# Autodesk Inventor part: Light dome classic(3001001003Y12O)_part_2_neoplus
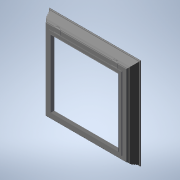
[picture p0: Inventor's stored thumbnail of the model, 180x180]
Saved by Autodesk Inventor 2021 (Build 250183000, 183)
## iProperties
Created: 2026-04
Part Number: Light dome classic(3001001003Y12O)_part_2_neoplus
Material: Generic
Catalog Web Link: www.3dfindit.com
Description: Light dome classic_part_2_neoplus-
Vendor: KINGSPAN
Document SubType Name: Modeling
Designer: psAdmin
Manufacturer: KINGSPAN
Mass: 9326.02 g
Surface Area: 18698.6 cm^2
Volume: 9326.02 cm^3
Density: 1 g/cm^3
Appearance: PSOLRGB-255-255-255
Category: PARTsolutions
Company: KINGSPAN
Title: Light dome classic(3001001003Y12O)_part_2_neoplus
Author: Cadenas PARTsolutions
PSOL_IDENT_0: {$CADENAS_DATA/23d-libs/kingspan_kla/light_dome_classic_neoplus/parts/part_2.prj},293 {VTYP=3D},{NB=
PSOL_IDENT_1: Light dome classic(3001001003Y12O)_part_2_neoplus},{LINA=Light dome classic(3001001003Y12O)_part_2_n
PSOL_IDENT_2: eoplus},{NN=Light dome classic_part_2_neoplus},{DATE=20.03.2025 09:30:52},{GEOMDATE=01.07.2024 06:23
PSOL_IDENT_3: :48},{VERSION=},{LINEID=10},{WBVAR=LODLEVEL,L,W,BA,SF,DP,OP,OC},{WBNUMERIC=W}  {NB=Light dome classi
PSOL_IDENT_4: c(3001001003Y12O)_part_2_neoplus},{LINA=Light dome classic(3001001003Y12O)_part_2_neoplus},{KT=DUMMY
PSOL_IDENT_5: },{IDNR=},{PN=Light dome classic},{LODLEVEL=300},{L=100},{W=100},{WX=100,150,200,250,300},{LX=1000},
PSOL_IDENT_6: {XWX=1000},{BA=3},{SF=Y},{SFX='Y','Yes','N','No'},{DRIVE=1},{DPX='1', 'Natural ventilation', '2' , '
PSOL_IDENT_7: NSHEV (natural smoke, heat exhaust ventilation)', '3', 'Fixed','4','NSHE'},{DP=1},{OPX='1','manualy'
PSOL_IDENT_8: ,'2','Linear drive 300 mm stroke 24 V and 230 V','3','Linear drive 500 mm stroke 24 V and 230 V'},{O
PSOL_IDENT_9: P=2},{OCX='O', 'Open', 'C', 'Closed'},{OC=O}
NB: Light dome classic(3001001003Y12O)_part_2_neoplus
NN: Light dome classic_part_2_neoplus
NBSYN: $PN.($LODLEVEL.$L.$W.$BA.$SF.$DP.$OP.$OC.)_part_2_neoplus
LINA: Light dome classic(3001001003Y12O)_part_2_neoplus
CATALOG: Light + Air
PN: Light dome classic
LODLEVEL: 300
L: 100
W: 100
BA: PVC base 50 cm
SF: Yes
DP: Natural ventilation
OP: Linear drive 300 mm stroke 24 V and 230 V
OC: Open
SUPPLIER: KINGSPAN
ARTICLENO: Light dome classic(3001001003Y12O)_part_2_neoplus
BOMINFO: Light dome classic(3001001003Y12O)_part_2_neoplus
CREATOR: CADENAS GmbH
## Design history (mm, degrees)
sketch "Sketch_1"
  geometry: L1 (-393, 334)-(-395.2, 334); L2 (-395.2, 334)-(-395.2, 327); L3 (-395.2, 327)-(-424, 327); L4 (-424, 327)-(-424, 316); L5 (-424, 316)-(-467.8, 316); L6 (-472, 311.8)-(-472, 306.773); L7 (-477, 298.113)-(-489.32, 291); L8 (-489.32, 291)-(-500.849, 274.535); L9 (-500.849, 274.535)-(-496.754, 271.668); L10 (-496.754, 271.668)-(-508.226, 255.284); L11 (-508.226, 255.284)-(-504.129, 252.415); L12 (-504.129, 252.415)-(-515.6, 236.032); L13 (-515.6, 236.032)-(-511.507, 233.166); L14 (-511.507, 233.166)-(-521.208, 219.311); L15 (-521.208, 219.311)-(-532.773, 219.311); L16 (-532.773, 219.311)-(-532.773, 204.131); L17 (-532.773, 204.131)-(-525.173, 204.131); L18 (-519.959, 217.26)-(-508.443, 233.706); L19 (-508.443, 233.706)-(-512.536, 236.572); L20 (-512.536, 236.572)-(-501.065, 252.955); L21 (-501.065, 252.955)-(-505.162, 255.824); L22 (-505.162, 255.824)-(-493.69, 272.208); L23 (-493.69, 272.208)-(-497.785, 275.075); L24 (-497.785, 275.075)-(-487.798, 289.339); L25 (-487.798, 289.339)-(-481.456, 293); L26 (-481.456, 293)-(-393, 293); L27 (-393, 293)-(-393, 334); A1 r 4.2 centre (-467.8, 311.8) between (-467.8, 316) and (-472, 311.8); A2 r 10 centre (-482, 306.773) between (-477, 298.113) and (-472, 306.773); A3 r 7.6 centre (-525.173, 211.731) between (-525.173, 204.131) and (-519.959, 217.26)
  constraints: 54 end point, 6 point on circle, 3 centre point
extrude "Extrusion1" join sketch "Sketch_1" stored distance "d0" = 2000; taper "d1" = 0 deg
sketch "Sketch_2"
  geometry: L1 (395.2, 334)-(393, 334); L2 (393, 334)-(393, 293); L3 (393, 293)-(481.456, 293); L4 (481.456, 293)-(487.798, 289.339); L5 (487.798, 289.339)-(497.785, 275.075); L6 (497.785, 275.075)-(493.69, 272.208); L7 (493.69, 272.208)-(505.162, 255.824); L8 (505.162, 255.824)-(501.065, 252.955); L9 (501.065, 252.955)-(512.536, 236.572); L10 (512.536, 236.572)-(508.443, 233.706); L11 (508.443, 233.706)-(519.959, 217.26); L12 (525.173, 204.131)-(532.77, 204.131); L13 (532.77, 204.131)-(532.77, 219.311); L14 (532.77, 219.311)-(521.208, 219.311); L15 (521.208, 219.311)-(511.507, 233.166); L16 (511.507, 233.166)-(515.6, 236.032); L17 (515.6, 236.032)-(504.129, 252.415); L18 (504.129, 252.415)-(508.226, 255.284); L19 (508.226, 255.284)-(496.754, 271.668); L20 (496.754, 271.668)-(500.849, 274.535); L21 (500.849, 274.535)-(489.32, 291); L22 (489.32, 291)-(477, 298.113); L23 (472, 306.773)-(472, 311.8); L24 (467.8, 316)-(424, 316); L25 (424, 316)-(424, 327); L26 (424, 327)-(395.2, 327); L27 (395.2, 327)-(395.2, 334); A1 r 7.6 centre (525.173, 211.731) between (519.959, 217.26) and (525.173, 204.131); A2 r 10 centre (482, 306.773) between (472, 306.773) and (477, 298.113); A3 r 4.2 centre (467.8, 311.8) between (472, 311.8) and (467.8, 316)
  constraints: 54 end point, 6 point on circle, 3 centre point
extrude "Extrusion2" join sketch "Sketch_2" stored distance "d2" = 2000; taper "d3" = 0 deg
sketch "Sketch_3"
  geometry: L1 (534.773, 204.131)-(534.773, 219.311); L2 (534.773, 219.311)-(521.208, 219.311); L3 (521.208, 219.311)-(511.507, 233.166); L4 (511.507, 233.166)-(515.6, 236.032); L5 (515.6, 236.032)-(504.129, 252.415); L6 (504.129, 252.415)-(508.226, 255.284); L7 (508.226, 255.284)-(496.754, 271.668); L8 (496.754, 271.668)-(500.849, 274.535); L9 (500.849, 274.535)-(489.32, 291); L10 (489.32, 291)-(477, 298.113); L11 (472, 306.773)-(472, 311.8); L12 (467.8, 316)-(424, 316); L13 (424, 316)-(424, 327); L14 (424, 327)-(395.2, 327); L15 (395.2, 327)-(395.2, 334); L16 (395.2, 334)-(393, 334); L17 (393, 334)-(393, 293); L18 (393, 293)-(481.456, 293); L19 (481.456, 293)-(487.798, 289.339); L20 (487.798, 289.339)-(497.785, 275.075); L21 (497.785, 275.075)-(493.69, 272.208); L22 (493.69, 272.208)-(505.162, 255.824); L23 (505.162, 255.824)-(501.065, 252.955); L24 (501.065, 252.955)-(512.536, 236.572); L25 (512.536, 236.572)-(508.443, 233.706); L26 (508.443, 233.706)-(519.959, 217.26); L27 (525.173, 204.131)-(534.773, 204.131); A1 r 10 centre (482, 306.773) between (472, 306.773) and (477, 298.113); A2 r 4.2 centre (467.8, 311.8) between (472, 311.8) and (467.8, 316); A3 r 7.6 centre (525.173, 211.731) between (519.959, 217.26) and (525.173, 204.131)
  constraints: 54 end point, 6 point on circle, 3 centre point
extrude "Extrusion3" join sketch "Sketch_3" stored distance "d4" = 2000; taper "d5" = 0 deg
sketch "Sketch_4"
  geometry: L1 (-395.2, 334)-(-395.2, 327); L2 (-395.2, 327)-(-424, 327); L3 (-424, 327)-(-424, 316); L4 (-424, 316)-(-467.8, 316); L5 (-472, 311.8)-(-472, 306.773); L6 (-477, 298.113)-(-489.32, 291); L7 (-489.32, 291)-(-500.849, 274.535); L8 (-500.849, 274.535)-(-496.754, 271.668); L9 (-496.754, 271.668)-(-508.226, 255.284); L10 (-508.226, 255.284)-(-504.129, 252.415); L11 (-504.129, 252.415)-(-515.6, 236.032); L12 (-515.6, 236.032)-(-511.507, 233.166); L13 (-511.507, 233.166)-(-521.208, 219.311); L14 (-521.208, 219.311)-(-532.77, 219.311); L15 (-532.77, 219.311)-(-532.77, 204.131); L16 (-532.77, 204.131)-(-525.173, 204.131); L17 (-519.959, 217.26)-(-508.443, 233.706); L18 (-508.443, 233.706)-(-512.536, 236.572); L19 (-512.536, 236.572)-(-501.065, 252.955); L20 (-501.065, 252.955)-(-505.162, 255.824); L21 (-505.162, 255.824)-(-493.69, 272.208); L22 (-493.69, 272.208)-(-497.785, 275.075); L23 (-497.785, 275.075)-(-487.798, 289.339); L24 (-487.798, 289.339)-(-481.456, 293); L25 (-481.456, 293)-(-393, 293); L26 (-393, 293)-(-393, 334); L27 (-393, 334)-(-395.2, 334); A1 r 4.2 centre (-467.8, 311.8) between (-467.8, 316) and (-472, 311.8); A2 r 10 centre (-482, 306.773) between (-477, 298.113) and (-472, 306.773); A3 r 7.6 centre (-525.173, 211.731) between (-525.173, 204.131) and (-519.959, 217.26)
  constraints: 54 end point, 6 point on circle, 3 centre point
extrude "Extrusion4" join sketch "Sketch_4" stored distance "d6" = 2000; taper "d7" = 0 deg
sketch "Sketch_5"
  geometry: L1 (-393, 357)-(-1093, 357); L2 (-1093, 357)-(-1093, 80.939); L3 (-1093, 80.939)-(-527.437, 180.866); L4 (-527.437, 180.866)-(-532.657, 210.409); L5 (-525.724, 219.311)-(-521.208, 219.311); L6 (-521.208, 219.311)-(-511.507, 233.166); L7 (-511.507, 233.166)-(-515.6, 236.032); L8 (-515.6, 236.032)-(-504.129, 252.415); L9 (-504.129, 252.415)-(-508.226, 255.284); L10 (-508.226, 255.284)-(-496.754, 271.668); L11 (-496.754, 271.668)-(-500.849, 274.535); L12 (-500.849, 274.535)-(-489.32, 291); L13 (-489.32, 291)-(-477, 298.113); L14 (-472, 306.773)-(-472, 311.8); L15 (-467.8, 316)-(-424, 316); L16 (-424, 316)-(-424, 327); L17 (-424, 327)-(-395.2, 327); L18 (-395.2, 327)-(-395.2, 334); L19 (-395.2, 334)-(-393, 334); L20 (-393, 334)-(-393, 357); A1 r 7.6 centre (-525.173, 211.731) between (-525.724, 219.311) and (-532.657, 210.409); A2 r 10 centre (-482, 306.773) between (-477, 298.113) and (-472, 306.773); A3 r 4.2 centre (-467.8, 311.8) between (-467.8, 316) and (-472, 311.8)
  constraints: 40 end point, 6 point on circle, 3 centre point
extrude "Extrusion5" cut sketch "Sketch_5" stored distance "d8" = 2000; taper "d9" = 0 deg
sketch "Sketch_6"
  geometry: L1 (1093, 80.939)-(1093, 357); L2 (1093, 357)-(393, 357); L3 (393, 357)-(393, 334); L4 (393, 334)-(395.2, 334); L5 (395.2, 334)-(395.2, 327); L6 (395.2, 327)-(424, 327); L7 (424, 327)-(424, 316); L8 (424, 316)-(467.8, 316); L9 (472, 311.8)-(472, 306.773); L10 (477, 298.113)-(489.32, 291); L11 (489.32, 291)-(500.849, 274.535); L12 (500.849, 274.535)-(496.754, 271.668); L13 (496.754, 271.668)-(508.226, 255.284); L14 (508.226, 255.284)-(504.129, 252.415); L15 (504.129, 252.415)-(515.6, 236.032); L16 (515.6, 236.032)-(511.507, 233.166); L17 (511.507, 233.166)-(521.208, 219.311); L18 (521.208, 219.311)-(525.724, 219.311); L19 (532.657, 210.409)-(527.437, 180.866); L20 (527.437, 180.866)-(1093, 80.939); A1 r 4.2 centre (467.8, 311.8) between (472, 311.8) and (467.8, 316); A2 r 10 centre (482, 306.773) between (472, 306.773) and (477, 298.113); A3 r 7.6 centre (525.173, 211.731) between (532.657, 210.409) and (525.724, 219.311)
  constraints: 40 end point, 6 point on circle, 3 centre point
extrude "Extrusion6" cut sketch "Sketch_6" stored distance "d10" = 2000; taper "d11" = 0 deg
sketch "Sketch_7"
  geometry: L1 (1093, 357)-(393, 357); L2 (393, 357)-(393, 334); L3 (393, 334)-(395.2, 334); L4 (395.2, 334)-(395.2, 327); L5 (395.2, 327)-(424, 327); L6 (424, 327)-(424, 316); L7 (424, 316)-(467.8, 316); L8 (472, 311.8)-(472, 306.773); L9 (477, 298.113)-(489.32, 291); L10 (489.32, 291)-(500.849, 274.535); L11 (500.849, 274.535)-(496.754, 271.668); L12 (496.754, 271.668)-(508.226, 255.284); L13 (508.226, 255.284)-(504.129, 252.415); L14 (504.129, 252.415)-(515.6, 236.032); L15 (515.6, 236.032)-(511.507, 233.166); L16 (511.507, 233.166)-(521.208, 219.311); L17 (521.208, 219.311)-(525.724, 219.311); L18 (532.657, 210.409)-(523.957, 161.171); L19 (523.957, 161.171)-(1093, 60.629); L20 (1093, 60.629)-(1093, 357); A1 r 4.2 centre (467.8, 311.8) between (472, 311.8) and (467.8, 316); A2 r 10 centre (482, 306.773) between (472, 306.773) and (477, 298.113); A3 r 7.6 centre (525.173, 211.731) between (532.657, 210.409) and (525.724, 219.311)
  constraints: 40 end point, 6 point on circle, 3 centre point
extrude "Extrusion7" cut sketch "Sketch_7" stored distance "d12" = 2000; taper "d13" = 0 deg
sketch "Sketch_8"
  geometry: L1 (-1093, 357)-(-1093, 60.629); L2 (-1093, 60.629)-(-523.957, 161.171); L3 (-523.957, 161.171)-(-532.657, 210.409); L4 (-525.724, 219.311)-(-521.208, 219.311); L5 (-521.208, 219.311)-(-511.507, 233.166); L6 (-511.507, 233.166)-(-515.6, 236.032); L7 (-515.6, 236.032)-(-504.129, 252.415); L8 (-504.129, 252.415)-(-508.226, 255.284); L9 (-508.226, 255.284)-(-496.754, 271.668); L10 (-496.754, 271.668)-(-500.849, 274.535); L11 (-500.849, 274.535)-(-489.32, 291); L12 (-489.32, 291)-(-477, 298.113); L13 (-472, 306.773)-(-472, 311.8); L14 (-467.8, 316)-(-424, 316); L15 (-424, 316)-(-424, 327); L16 (-424, 327)-(-395.2, 327); L17 (-395.2, 327)-(-395.2, 334); L18 (-395.2, 334)-(-393, 334); L19 (-393, 334)-(-393, 357); L20 (-393, 357)-(-1093, 357); A1 r 7.6 centre (-525.173, 211.731) between (-525.724, 219.311) and (-532.657, 210.409); A2 r 10 centre (-482, 306.773) between (-477, 298.113) and (-472, 306.773); A3 r 4.2 centre (-467.8, 311.8) between (-467.8, 316) and (-472, 311.8)
  constraints: 40 end point, 6 point on circle, 3 centre point
extrude "Extrusion8" cut sketch "Sketch_8" stored distance "d14" = 2000; taper "d15" = 0 deg
sketch "Sketch_13"
  geometry: L1 (-319.461, 425.103)-(-318, 425); L2 (-318, 425)-(-316, 425); L3 (-316, 425)-(-316, 474.531); L4 (-316, 474.531)-(-303.205, 484.473); L5 (-308.009, 483.974)-(-307.436, 485.954); L6 (-304.441, 486.046)-(-318, 475.51); L7 (-318, 475.51)-(-318, 429); L8 (-318, 429)-(-319.461, 425.103); A1 r 4.5 centre (-306, 488) between (-303.205, 484.473) and (-308.009, 483.974); A2 r 2.5 centre (-306, 488) between (-304.441, 486.046) and (-307.436, 485.954)
  constraints: 16 end point, 4 point on circle, 2 centre point
extrude "Extrusion9" join sketch "Sketch_13" distance "d16" = 70; taper "d17" = 0 deg
sketch "Sketch_14"
  geometry: L1 (-319.461, 425.103)-(-318, 425); L2 (-318, 425)-(-316, 425); L3 (-316, 425)-(-316, 474.531); L4 (-316, 474.531)-(-303.205, 484.473); L5 (-308.009, 483.974)-(-307.436, 485.954); L6 (-304.441, 486.046)-(-318, 475.51); L7 (-318, 475.51)-(-318, 429); L8 (-318, 429)-(-319.461, 425.103); A1 r 4.5 centre (-306, 488) between (-303.205, 484.473) and (-308.009, 483.974); A2 r 2.5 centre (-306, 488) between (-304.441, 486.046) and (-307.436, 485.954)
  constraints: 16 end point, 4 point on circle, 2 centre point
extrude "Extrusion10" join sketch "Sketch_14" distance "d18" = 70; taper "d19" = 0 deg
sketch "Sketch_15"
  geometry: L1 (299, 502.5)-(299, 481.42); L2 (299, 481.42)-(317.5, 481.42); L3 (317.5, 481.42)-(317.5, 492.5); L4 (317.5, 492.5)-(350.5, 492.5); L5 (350.5, 492.5)-(350.5, 481.42); L6 (350.5, 481.42)-(369, 481.42); L7 (369, 481.42)-(369, 502.5); L8 (369, 502.5)-(299, 502.5)
  constraints: 16 end point
extrude "Extrusion11" cut sketch "Sketch_15" distance "d20" = 20; taper "d21" = 0 deg
sketch "Sketch_16"
  geometry: L1 (-369, 481.42)-(-350.5, 481.42); L2 (-350.5, 481.42)-(-350.5, 492.5); L3 (-350.5, 492.5)-(-317.5, 492.5); L4 (-317.5, 492.5)-(-317.5, 481.42); L5 (-317.5, 481.42)-(-299, 481.42); L6 (-299, 481.42)-(-299, 502.5); L7 (-299, 502.5)-(-369, 502.5); L8 (-369, 502.5)-(-369, 481.42)
  constraints: 16 end point
extrude "Extrusion12" cut sketch "Sketch_16" distance "d22" = 20; taper "d23" = 0 deg
sketch "Sketch_21"
  geometry: L1 (-521.208, 224.311)-(-555.173, 224.311); L2 (-555.173, 224.311)-(-555.173, 189.311); L3 (-555.173, 189.311)-(-525.173, 189.311); L4 (-525.173, 189.311)-(-525.173, 204.131); L5 (-525.724, 219.311)-(-521.208, 219.311); L6 (-521.208, 219.311)-(-521.208, 224.311); A1 r 7.6 centre (-525.173, 211.731) between (-525.724, 219.311) and (-525.173, 204.131)
  constraints: 12 end point, 2 point on circle, 1 centre point
extrude "Extrusion13" cut sketch "Sketch_21" stored distance "d24" = 2000; taper "d25" = 0 deg
sketch "Sketch_22"
  geometry: L1 (555.173, 224.311)-(521.208, 224.311); L2 (521.208, 224.311)-(521.208, 219.311); L3 (521.208, 219.311)-(525.724, 219.311); L4 (525.173, 204.131)-(525.173, 189.311); L5 (525.173, 189.311)-(555.173, 189.311); L6 (555.173, 189.311)-(555.173, 224.311); A1 r 7.6 centre (525.173, 211.731) between (525.173, 204.131) and (525.724, 219.311)
  constraints: 12 end point, 2 point on circle, 1 centre point
extrude "Extrusion14" cut sketch "Sketch_22" stored distance "d26" = 2000; taper "d27" = 0 deg
sketch "Sketch_23"
  geometry: L1 (542.77, 224.311)-(521.208, 224.311); L2 (521.208, 224.311)-(521.208, 219.311); L3 (521.208, 219.311)-(525.724, 219.311); L4 (525.173, 204.131)-(525.173, 189.311); L5 (525.173, 189.311)-(542.77, 189.311); L6 (542.77, 189.311)-(542.77, 224.311); A1 r 7.6 centre (525.173, 211.731) between (525.173, 204.131) and (525.724, 219.311)
  constraints: 12 end point, 2 point on circle, 1 centre point
extrude "Extrusion15" cut sketch "Sketch_23" stored distance "d28" = 2000; taper "d29" = 0 deg
sketch "Sketch_24"
  geometry: L1 (-542.77, 224.311)-(-542.77, 189.311); L2 (-542.77, 189.311)-(-525.173, 189.311); L3 (-525.173, 189.311)-(-525.173, 204.131); L4 (-525.724, 219.311)-(-521.208, 219.311); L5 (-521.208, 219.311)-(-521.208, 224.311); L6 (-521.208, 224.311)-(-542.77, 224.311); A1 r 7.6 centre (-525.173, 211.731) between (-525.724, 219.311) and (-525.173, 204.131)
  constraints: 12 end point, 2 point on circle, 1 centre point
extrude "Extrusion16" cut sketch "Sketch_24" stored distance "d30" = 2000; taper "d31" = 0 deg
node "IP_2_XY"
node "IP_2_YZ"
node "IP_2_ZX"
node "IP_2_X"
node "IP_2_Y"
node "IP_2_Z"
node "IP_2_Center"
node "IP_for_part_3_XY"
node "IP_for_part_3_YZ"
node "IP_for_part_3_ZX"
node "IP_for_part_3_X"
node "IP_for_part_3_Y"
node "IP_for_part_3_Z"
node "IP_for_part_3_Center"
node "IP_for_part_8_1_XY"
node "IP_for_part_8_1_YZ"
node "IP_for_part_8_1_ZX"
node "IP_for_part_8_1_X"
node "IP_for_part_8_1_Y"
node "IP_for_part_8_1_Z"
node "IP_for_part_8_1_Center"
node "IP_for_part_8_2_XY"
node "IP_for_part_8_2_YZ"
node "IP_for_part_8_2_ZX"
node "IP_for_part_8_2_X"
node "IP_for_part_8_2_Y"
node "IP_for_part_8_2_Z"
node "IP_for_part_8_2_Center"
node "IP_for_part_8_3_XY"
node "IP_for_part_8_3_YZ"
node "IP_for_part_8_3_ZX"
node "IP_for_part_8_3_X"
node "IP_for_part_8_3_Y"
node "IP_for_part_8_3_Z"
node "IP_for_part_8_3_Center"
node "IP_for_part_8_4_XY"
node "IP_for_part_8_4_YZ"
node "IP_for_part_8_4_ZX"
node "IP_for_part_8_4_X"
node "IP_for_part_8_4_Y"
node "IP_for_part_8_4_Z"
node "IP_for_part_8_4_Center"
node "IP_for_part_8_5_XY"
node "IP_for_part_8_5_YZ"
node "IP_for_part_8_5_ZX"
node "IP_for_part_8_5_X"
node "IP_for_part_8_5_Y"
node "IP_for_part_8_5_Z"
node "IP_for_part_8_5_Center"
node "IP_for_part_9_XY"
node "IP_for_part_9_YZ"
node "IP_for_part_9_ZX"
node "IP_for_part_9_X"
node "IP_for_part_9_Y"
node "IP_for_part_9_Z"
node "IP_for_part_9_Center"
body "Solid1"
other parameters: "d32" = 0
